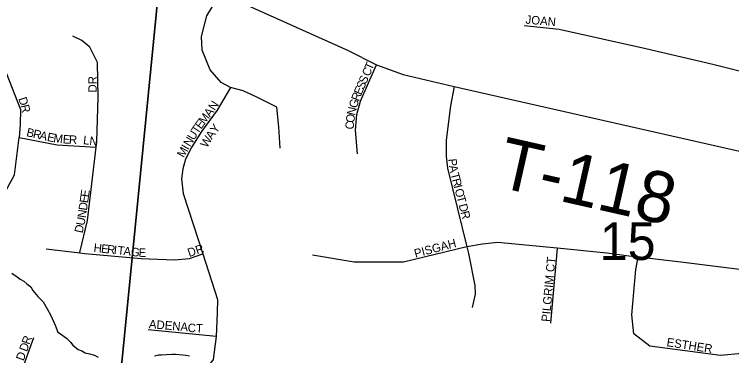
# Model space of a CAD drawing. Extents: x 1310247 to 1552180, y 377264 to 706493.
# Drawn here: x 1433472 to 1437687, y 484836 to 486843 of the extents above; entities that cross this region are included whole.
import ezdxf

# ---------------------------------------------------------------- set-up
doc = ezdxf.new("R2010")
doc.units = 0
for name, color, linetype in [('GM_X_Minor_River', 7, 'Continuous'), ('GM_X_Section', 7, 'Continuous'), ('GM_X_Section_Text', 7, 'Continuous'), ('GM_X_Township_Road', 7, 'Continuous'), ('GM_X_Township_Road_Text', 7, 'Continuous'), ('GM_X_Township_Subdivision', 7, 'Continuous'), ('GM_X_Township_Subdivision_Text', 7, 'Continuous')]:
    doc.layers.add(name, color=color, linetype=linetype)

msp = doc.modelspace()

# ---------------------------------------------------------------- linework, layer by layer
at = {"layer": 'GM_X_Minor_River'}
for points in [[(1433457.8, 485320.2), (1433489.3, 485299.1), (1433507, 485286.6), (1433526.7, 485273.9), (1433544.3, 485259.3)], [(1433544.3, 485259.3), (1433567.9, 485240.5), (1433581.3, 485220.1), (1433610.3, 485183), (1433641.6, 485152), (1433664.4, 485111.1), (1433685.4, 485072.3), (1433711.8, 485015.3), (1433726.7, 484974.8), (1433748.3, 484960), (1433779.8, 484937), (1433801.2, 484916.3), (1433814.8, 484897.8), (1433846.1, 484872.7), (1433867.9, 484864), (1433887.7, 484853.4), (1433913.6, 484846.6), (1433943.5, 484839.6), (1433965.2, 484826.9)], [(1434294.6, 484835), (1434318.8, 484840.2), (1434336.9, 484841.7), (1434365, 484842.8), (1434397.2, 484843.9), (1434419.3, 484845.2), (1434441.3, 484842.5), (1434461.3, 484839.9), (1434479.3, 484839.3), (1434501.3, 484834.6)]]:
    msp.add_lwpolyline(points, dxfattribs=at)
at = {"layer": 'GM_X_Section'}
for points in [[(1434523.9, 489065.4), (1433994.3, 483685), (1428777.4, 483907.1), (1429255.8, 489324.6)], [(1434523.9, 489065.4), (1440171.6, 487550.2), (1439630.2, 482211.5), (1433994.3, 483685)]]:
    msp.add_lwpolyline(points, close=True, dxfattribs=at)
at = {"layer": 'GM_X_Township_Road'}
msp.add_lwpolyline([(1433156.7, 487398.1), (1433502.2, 487239), (1433611.4, 487193.7), (1433704.9, 487168.8), (1433909.3, 487142.8), (1433997.1, 487130.8), (1434309.7, 487098), (1434504.5, 487035.7), (1434679.1, 486962.5), (1434825.3, 486902.8), (1435430.5, 486633.2), (1435599.6, 486546.5), (1435757.5, 486490.2), (1436056, 486418.9), (1437732.5, 486039), (1438013.5, 485971.1), (1438126.7, 485941.5), (1438384.8, 485877.1), (1438836.2, 485767.5), (1439259.5, 485656.9), (1439362.8, 485657.9), (1439422.7, 485657)], dxfattribs=at)
at = {"layer": 'GM_X_Township_Subdivision'}
for points in [[(1435034.7, 486055.4), (1435026.3, 486181.4), (1435015.1, 486298), (1434897.7, 486355.7), (1434816, 486392.6), (1434742.7, 486413.3), (1434686.9, 486441.5), (1434621.8, 486517.1), (1434575.2, 486631.5), (1434570.7, 486713.7), (1434602, 486834), (1434679.1, 486962.5)], [(1433310.7, 486752.6), (1433313.9, 486748.4), (1433356.6, 486653), (1433423.4, 486498.5), (1433508.5, 486283.9), (1433506, 486194.7), (1433499.7, 486118.2)], [(1436466.8, 486777.1), (1436672.8, 486755.9), (1437182.9, 486642.3), (1437576.8, 486549.4), (1437840, 486484.2), (1438059.3, 486433.4), (1438386, 486351.3), (1438628.1, 486292), (1438820.3, 486273.4), (1438964.2, 486292), (1439216.4, 486331)], [(1433856.4, 485440.3), (1433857.1, 485443.2), (1433901.5, 485630), (1433953, 486061.3), (1433957, 486094.5), (1433964.4, 486353.5), (1433960.7, 486560.8), (1433916.4, 486649.2), (1433867.6, 486689.1), (1433816.4, 486715)], [(1435488.7, 486022.3), (1435475.8, 486162.9), (1435485, 486253.6), (1435505.9, 486332.4), (1435552.3, 486441), (1435599.6, 486546.5)], [(1436056, 486418.9), (1436035.2, 486305.6), (1436008.5, 486103.3), (1436009.1, 486008.9), (1436018, 485937.9), (1436130, 485475.8), (1436139.8, 485436.2), (1436177.2, 485248.2), (1436179.4, 485198), (1436162.5, 485118.3)], [(1434742.7, 486413.3), (1434663.3, 486279.1), (1434571.1, 486154.5), (1434513.9, 486064.1), (1434477.4, 485991.2), (1434461.8, 485934.5), (1434454.4, 485876.4), (1434463.6, 485790.1), (1434579.8, 485434.4), (1434665.6, 485166.8), (1434663.1, 485087.6)], [(1433091.9, 485221.3), (1433131.8, 485344.2), (1433259.9, 485563.3), (1433325.2, 485641.1), (1433379.2, 485729), (1433473.3, 485899.7), (1433499.7, 486118.2)], [(1433499.7, 486118.2), (1433723.2, 486076.2), (1433953, 486061.3)], [(1437083.4, 485421.6), (1436954.4, 485439.3), (1436661, 485468.4), (1436311.9, 485501.6), (1436223.6, 485492.2), (1436130, 485475.8), (1435759.3, 485386.3), (1435469.2, 485386.2), (1435223.1, 485426)], [(1433659.6, 485464.5), (1433856.4, 485440.3), (1433885.3, 485436.7), (1434216.8, 485407.9), (1434413.9, 485398.7), (1434501.7, 485407.6), (1434579.8, 485434.4)], [(1436661, 485468.4), (1436622.7, 485027.3)], [(1438523.8, 484583), (1438298.6, 484875), (1438213.5, 484984), (1438090.2, 485092.9), (1437891.5, 485280.2), (1437733.8, 485343.5), (1437389.1, 485386.2), (1437137.1, 485414.3), (1437083.4, 485421.6)], [(1438090.2, 485092.9), (1437947.5, 484969.3), (1437848.8, 484892.7), (1437748.6, 484848.4), (1437621.9, 484836.7), (1437206.3, 484892.7), (1437112, 484965.3), (1437099.9, 485076.2), (1437123.8, 485343.5), (1437137.1, 485414.3)], [(1434663.1, 485087.6), (1434658.6, 484948.2), (1434640.1, 484813.2), (1434555, 484698.4), (1434466.2, 484646.6), (1434251.6, 484539.3), (1434122.1, 484472.7), (1434053.7, 484363.5), (1434010.4, 484124.9)], [(1434658.6, 484948.2), (1434259, 484987.1)], [(1433584.2, 484941.3), (1433457.6, 484588.8), (1433348.7, 484161.1), (1433343.6, 484128.1)]]:
    msp.add_lwpolyline(points, dxfattribs=at)

# ---------------------------------------------------------------- texts
at = {"layer": 'GM_X_Section_Text'}
msp.add_text('15', height=221, rotation=0, dxfattribs=at).set_placement((1436911.3, 485398.6))
at = {"layer": 'GM_X_Township_Road_Text'}
msp.add_text('T-118', height=300, rotation=347.2579, dxfattribs=at).set_placement((1436297.1, 485831.5))
at = {"layer": 'GM_X_Township_Subdivision_Text'}
for s, rotation, p in [('JOAN', 355.1005, (1436474.3, 486788.7)), ('T', 66.5453, (1435573.3, 486510.4)), ('C', 66.5319, (1435557.6, 486474.1)), ('DR', 90, (1433956.1, 486383.3)), ('S', 66.5341, (1435538.3, 486429.7)), ('E', 66.6256, (1435510.3, 486365.1)), ('S', 66.5521, (1435524.3, 486397.4)), ('R', 68.4534, (1435495.9, 486328.7)), ('D', 288.39, (1433494.7, 486347.2)), ('N', 57.0406, (1434649.7, 486273.4)), ('G', 72.9198, (1435483.4, 486287.6)), ('R', 282.3721, (1433508.2, 486306.8)), ('N', 76.8596, (1435473.6, 486245.6)), ('M', 53.2193, (1434589.7, 486192.9)), ('A', 53.321, (1434621.4, 486235.2)), ('O', 83.9012, (1435469.2, 486203.5)), ('E', 53.8732, (1434569, 486164.6)), ('Y', 53.4142, (1434657.2, 486139.1)), ('C', 84.4054, (1435465.3, 486164.2)), ('B', 346.9076, (1433539.4, 486127.6)), ('R', 346.9076, (1433577.9, 486118.7)), ('U', 58.1441, (1434527, 486098.6)), ('T', 56.6623, (1434550.1, 486135.7)), ('A', 346.9076, (1433616.5, 486109.7)), ('E', 348.749, (1433661.1, 486099.3)), ('M', 352.4317, (1433699.1, 486091.9)), ('E', 356.1144, (1433754.9, 486084.6)), ('R', 357.9557, (1433791.8, 486082.1)), ('LN', 353.6571, (1433874.1, 486080.1)), ('N', 58.86, (1434504.3, 486061.1)), ('W', 59.1487, (1434603.9, 486054.7)), ('A', 55.8522, (1434632.8, 486103.2)), ('I', 60.1684, (1434493.6, 486042.3)), ('M', 60.5951, (1434467.7, 485996.3)), ('P', 275.2946, (1436020.9, 485992.4)), ('A', 281.4169, (1436025, 485951.6)), ('T', 284.5689, (1436034.4, 485905.5)), ('R', 284.6168, (1436043.2, 485871.4)), ('I', 284.6034, (1436053.2, 485833.1)), ('E', 81.8755, (1433909.3, 485765.8)), ('O', 284.6244, (1436058.8, 485811.8)), ('E', 81.8755, (1433904.3, 485731)), ('T', 284.6261, (1436069.9, 485769.2)), ('D', 81.8759, (1433898.1, 485687.4)), ('D', 284.6167, (1436082.1, 485722.4)), ('N', 81.504, (1433891.5, 485643.5)), ('R', 284.6284, (1436093.2, 485679.8)), ('U', 78.6753, (1433882.4, 485597.8)), ('D', 77.5648, (1433872.7, 485553.8)), ('H', 353.8577, (1433935.8, 485446.7)), ('E', 353.8408, (1433979.5, 485442)), ('R', 353.8597, (1434014.5, 485438.2)), ('DR', 18.4368, (1434499.3, 485415.4)), ('PISGAH', 14.8592, (1435828.7, 485411.2)), ('I', 353.8457, (1434053.9, 485434)), ('T', 353.8613, (1434075.8, 485431.6)), ('A', 353.8469, (1434110.8, 485427.8)), ('G', 353.8584, (1434154.5, 485423.1)), ('E', 356.6588, (1434200.9, 485418.2)), ('PILGRIM CT', 84.8718, (1436618.1, 485033.4)), ('ADENA', 355.3335, (1434261.1, 484997.9)), ('CT', 356.8158, (1434489.6, 484975.9)), ('R', 70.2939, (1433560.3, 484897.5)), ('ESTHER', 351.2545, (1437302.1, 484892.2)), ('D', 70.3035, (1433545.5, 484856.1)), ('D', 70.3039, (1433526.2, 484802.2))]:
    msp.add_text(s, height=50, rotation=rotation, dxfattribs=at).set_placement(p)

doc.saveas('drawing.dxf')
